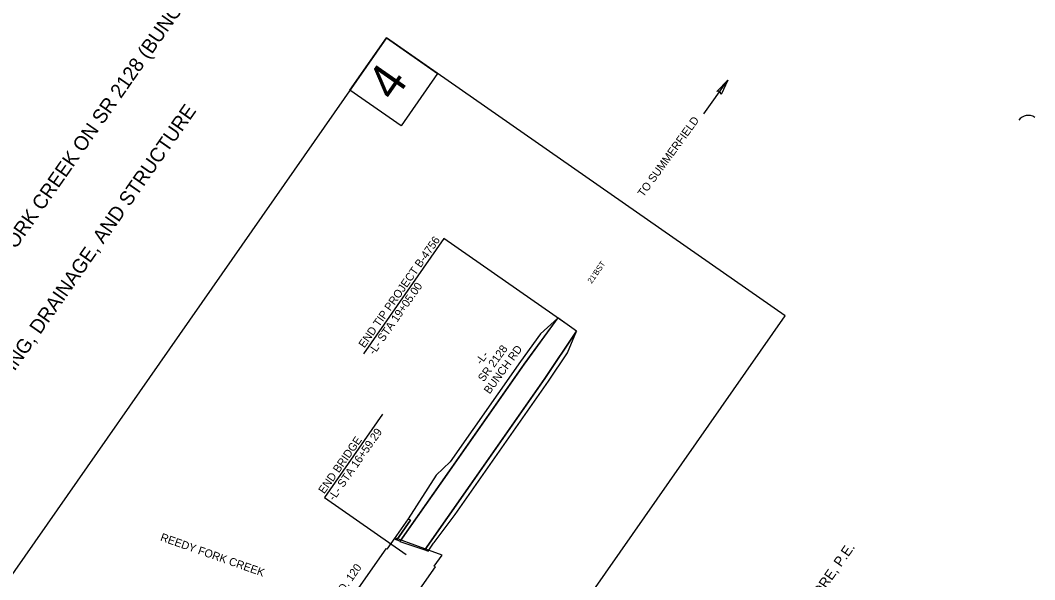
# Model space of a CAD drawing. Extents: x 1731327 to 1735374, y 884856 to 889832.
# Drawn here: x 1731919 to 1732806, y 885598 to 886088 of the extents above; entities that cross this region are included whole.
import ezdxf

# ---------------------------------------------------------------- set-up
doc = ezdxf.new("R2010")
doc.units = 0
for name, color, linetype in [('Exist Horizontal Baseline Alignment', 7, 'Continuous'), ('Exist Horizontal Baseline Alignment Direction Label', 7, 'Continuous'), ('Exist Horizontal Baseline Alignment Station Label', 7, 'Continuous'), ('Exist Hydro River Flow Arrow CELL', 7, 'Continuous'), ('Exist Other Culture Area Outline', 7, 'Continuous'), ('Exist Roads EOP', 7, 'Continuous'), ('Exist Structure Minor Pipes RCP 24 Inch', 7, 'Continuous'), ('Exist Vegetation Shrub CELL', 7, 'Continuous')]:
    doc.layers.add(name, color=color, linetype=linetype)

msp = doc.modelspace()

# ---------------------------------------------------------------- linework, layer by layer
at = {"layer": 'Exist Horizontal Baseline Alignment'}
msp.add_line((1732516.39, 886006.4), (1732537.36, 886035.7), dxfattribs=at)
at = {"layer": 'Exist Horizontal Baseline Alignment Direction Label'}
msp.add_lwpolyline([(1732527.72, 886025.97), (1732537.36, 886035.7), (1732531.55, 886023.2), (1732530.57, 886025.99)], close=True, dxfattribs=at)
at = {"layer": 'Exist Hydro River Flow Arrow CELL'}
msp.add_arc((1732800.15, 885994.95), 10, 55.09106, 145.09106, dxfattribs=at)
at = {"layer": 'Exist Other Culture Area Outline'}
for p, q in [((1732289.24, 885897.03), (1732218.94, 885796.14)), ((1732396.98, 885821.85), (1732289.24, 885897.03)), ((1732235.54, 885743.25), (1732184.69, 885670.37)), ((1732184.69, 885670.37), (1732256.14, 885620.51))]:
    msp.add_line(p, q, dxfattribs=at)
msp.add_lwpolyline([(1732238.91, 886072.74), (1731769.46, 885400.02), (1732118.14, 885156.7), (1732587.59, 885829.41)], close=True, dxfattribs=at)
at = {"layer": 'Exist Structure Minor Pipes RCP 24 Inch'}
for p, q in [((1732388.79, 885827.58), (1732359.31, 885787.18)), ((1732359.31, 885787.18), (1732388.78, 885827.57)), ((1732388.78, 885827.57), (1732373.72, 885813.72)), ((1732388.78, 885827.57), (1732388.78, 885827.57)), ((1732405.17, 885816.12), (1732388.79, 885827.58)), ((1732373.72, 885813.72), (1732356.03, 885789.48)), ((1732377.33, 885774.57), (1732405.17, 885816.12)), ((1732405.17, 885816.12), (1732377.33, 885774.57)), ((1732397.32, 885797.21), (1732405.17, 885816.12)), ((1732380.63, 885772.31), (1732397.32, 885797.21)), ((1732359.31, 885787.18), (1732293.96, 885693.77)), ((1732293.96, 885693.77), (1732359.31, 885787.18)), ((1732356.03, 885789.48), (1732294.68, 885701.78)), ((1732311.99, 885681.16), (1732377.33, 885774.57)), ((1732377.33, 885774.57), (1732311.99, 885681.16)), ((1732298.87, 885655.44), (1732380.63, 885772.31)), ((1732294.68, 885701.78), (1732282.48, 885690.09)), ((1732293.96, 885693.77), (1732250.74, 885631.89)), ((1732250.98, 885632.34), (1732293.96, 885693.77)), ((1732282.48, 885690.09), (1732257.97, 885651.92)), ((1732272.38, 885624.55), (1732311.99, 885681.16)), ((1732311.99, 885681.16), (1732272.38, 885624.55)), ((1732257.97, 885651.92), (1732245.63, 885634.28)), ((1732259.88, 885650.58), (1732247.9, 885633.46)), ((1732247.9, 885633.46), (1732259.88, 885650.58)), ((1732257.97, 885651.92), (1732259.88, 885650.58)), ((1732259.88, 885650.58), (1732257.97, 885651.92)), ((1732245.63, 885634.28), (1732247.9, 885633.46)), ((1732247.9, 885633.46), (1732250.98, 885632.34)), ((1732250.74, 885631.89), (1732272.38, 885624.55)), ((1732272.38, 885624.55), (1732275.3, 885623.49)), ((1732275.3, 885623.49), (1732280.17, 885630.45))]:
    msp.add_line(p, q, dxfattribs=at)
msp.add_lwpolyline([(1732280.17, 885630.45), (1732280.65, 885631.08), (1732298.87, 885655.44)], dxfattribs=at)
msp.add_lwpolyline([(1732163.68, 885517.13), (1732205.03, 885502.1), (1732211.91, 885511.93), (1732213.12, 885511.49), (1732281.91, 885609.82), (1732280.69, 885610.26), (1732287.56, 885620.08), (1732246.22, 885635.13), (1732239.34, 885625.29), (1732238.37, 885625.65), (1732169.58, 885527.32), (1732170.56, 885526.96)], close=True, dxfattribs=at)
at = {"layer": 'Exist Vegetation Shrub CELL'}
msp.add_lwpolyline([(1732238.91, 886072.74), (1732283.63, 886041.53), (1732251.7, 885995.79), (1732206.99, 886026.99)], close=True, dxfattribs=at)

# ---------------------------------------------------------------- texts
at = {"layer": 'Exist Horizontal Baseline Alignment'}
for s, rotation, p in [('TO SUMMERFIELD', 54.06605, (1732463.62, 885932.94)), ('END TIP PROJECT B-4756', 55.02513, (1732219.62, 885800.83)), ('-L- STA 19+05.00', 55.02513, (1732228.23, 885794.81)), ('SR 2128', 54.06605, (1732323.94, 885771.17)), ('BUNCH RD ', 54.06605, (1732329.16, 885760.48)), ('-L-', 54.06605, (1732321.85, 885786.18)), ('REEDY FORK CREEK', 340.5647, (1732040.59, 885632.9))]:
    msp.add_text(s, height=7, rotation=rotation, dxfattribs=at).set_placement(p)
at = {"layer": 'Exist Horizontal Baseline Alignment Station Label'}
for s, p in [('BRIDGE NO. 120 OVER REEDY FORK CREEK ON SR 2128 (BUNCH ROAD)', (1731765.8, 885674.04)), ('GRADING, PAVING, DRAINAGE, AND STRUCTURE', (1731844.56, 885681.48))]:
    msp.add_text(s, height=12.5001, rotation=55.09106, dxfattribs=at).set_placement(p)
at = {"layer": 'Exist Hydro River Flow Arrow CELL'}
msp.add_text('JEFFREY W. MOORE, P.E.', height=8.7498, rotation=55.09106, dxfattribs=at).set_placement((1732565.79, 885507.71))
at = {"layer": 'Exist Roads EOP'}
for s, height, p in [("21'BST", 5, (1732418.36, 885857.28)), ('-L- STA 16+59.29', 7, (1732193.1, 885667.1)), ('END BRIDGE', 7, (1732184.48, 885673.11)), ('BRIDGE NO. 120', 7, (1732175.6, 885549.12))]:
    msp.add_text(s, height=height, rotation=55.09106, dxfattribs=at).set_placement(p)
at = {"layer": 'Exist Vegetation Shrub CELL'}
msp.add_text('4', height=31.34, rotation=55.09106, dxfattribs=at).set_placement((1732245.51, 886016.09))

doc.saveas('drawing.dxf')
